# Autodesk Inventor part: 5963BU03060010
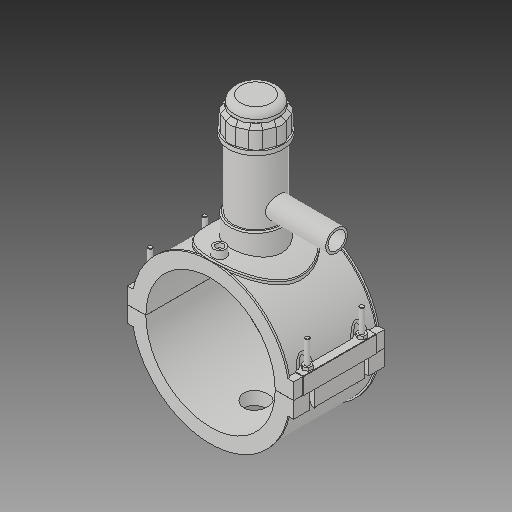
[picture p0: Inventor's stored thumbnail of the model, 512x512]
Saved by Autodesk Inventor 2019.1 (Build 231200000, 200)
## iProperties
Created: 2017-07
Part Number: 5963BU03060010
Material: Generic
Description: PLASSON TAPPING SADDLE 6''IPS x 1''CTS
Document SubType Name: Modeling
Designer: KIM
Mass: 1712.7 g
Surface Area: 2671.49 cm^2
Volume: 1712.7 cm^3
Density: 1 g/cm^3
Appearance: Default
Author: KIM
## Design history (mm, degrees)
derived "5963B.ipt"
feature "Solid1::5963B.ipt"
feature "Solid2::5963B.ipt"
feature "Solid4::5963B.ipt"
feature "Solid5::5963B.ipt"
tag "TaggingFeature1"
body "Solid1"
body "Solid2"
other parameters: "d0" = 168, "d2" = 215.9, "d3" = 42, "d4" = 118.11, "d5" = 0, "d6" = 0.1, "d8" = 0, "d19" = 6, "d20" = 6, "d21" = 70.866, "d23" = 0, "d24" = 35.433, "d26" = 0, "d29" = 3, "d30" = 56, "d31" = 6, "d32" = 0, "d33" = 0, "d34" = 0.6, "d40" = 104.832, "d41" = 117.6, "d43" = 0, "d45" = 0, "d47" = 171.666, "d70" = 15, "d72" = 0, "d73" = 6, "d75" = 5, "d76" = 0, "d77" = 8.4, "d78" = 114, "d79" = 15, "d80" = 47.244, "d82" = 5 deg, "d84" = 4, "d85" = 14, "d86" = 0, "d87" = 3, "d88" = 0, "d89" = 1, "d90" = 1, "d91" = 94.488, "d92" = 0, "d93" = 0.5, "d94" = 88.42105, "d96" = 205.632, "d97" = 2.3622, "d98" = 0, "d102" = 1.68, "d120" = 140 deg, "d121" = 24.228, "d122" = 20 deg, "d123" = 403.2, "d124" = 120.96, "d126" = 0, "d143" = 173.04, "d145" = 25.84615, "d149" = 2.52, "d150" = 28.43077, "d153" = 118.11, "d154" = 0, "d156" = 100.8, "d157" = 160 deg, "d159" = 6.72, "d161" = 2.52, "d162" = 70.866, "d163" = 0, "d164" = 84, "d167" = 16.8, "d168" = 98.34146, "d170" = 3.2805, "d172" = 0, "d173" = 1, "d175" = 84, "d176" = 20 deg, "d177" = 11.76, "d178" = 33.6, "d180" = 0, "d183" = 13.44, "d184" = 9.408, "d185" = 38.38575, "d186" = 38.38575, "d187" = 100.8, "d188" = 10.08, "d189" = 11.76, "d190" = 0, "d191" = 151.2, "d193" = 6.1236, "d194" = 4.13385, "d195" = 90 deg, "d197" = 0, "d199" = 0, "d200" = 16.8, "d202" = 0, "d203" = 177.038, "d204" = 67.032, "d205" = 49.392, "d206" = 59.976, "d207" = 132.7785, "d208" = 138.08964, "d209" = 164.64534, "d210" = 60.6816, "d211" = 70.56, "d212" = 56.448, "d213" = 45.7191, "d216" = 0, "d217" = 16.8, "d218" = 8.4, "d219" = 1.68, "d222" = 168, "d224" = 0, "d230" = 5.04, "d233" = 6, "d236" = 107.95, "d237" = 35.433, "d238" = 6.02433, "d240" = 35.433, "d241" = 35.433, "d242" = 35.433, "d243" = 6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
